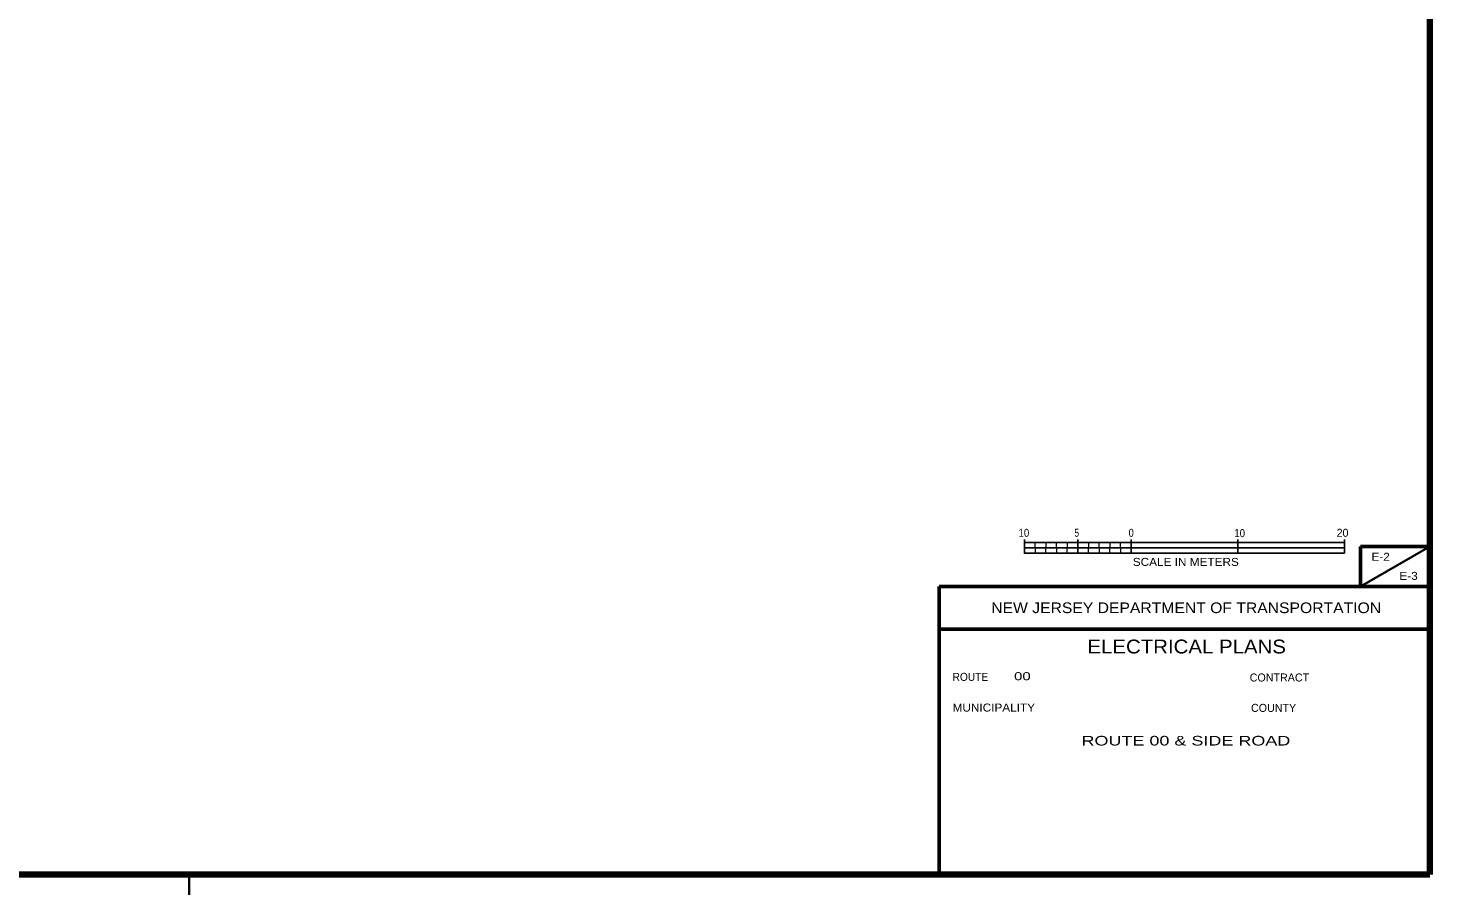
# Model space of a CAD drawing. Extents: x 168203 to 169863, y 223196 to 223870.
# Drawn here: x 169229.9 to 169361.3, y 223366.7 to 223448 of the extents above; entities that cross this region are included whole.
import ezdxf
from ezdxf.enums import TextEntityAlignment as Align

# ---------------------------------------------------------------- set-up
doc = ezdxf.new("R2010")
doc.units = 0
doc.header["$LTSCALE"] = 0.3
doc.layers.add('1', color=7, linetype='Continuous', lineweight=13)
doc.layers.add('25', color=7, linetype='Continuous', lineweight=35)

msp = doc.modelspace()

# ---------------------------------------------------------------- linework, layer by layer
at = {"layer": '1', "lineweight": 25}
for p, q in [((169323.2833, 223399.7226), (169353.2833, 223399.7226)), ((169325.1233, 223399.7226), (169326.1433, 223399.7226)), ((169327.1633, 223399.7226), (169328.1833, 223399.7226)), ((169328.2833, 223400.0201), (169328.2833, 223398.7226)), ((169329.2033, 223399.7226), (169330.2233, 223399.7226)), ((169331.2433, 223399.7226), (169332.2633, 223399.7226)), ((169333.2833, 223400.0201), (169333.2833, 223398.7226)), ((169343.2833, 223400.0201), (169343.2833, 223398.7226)), ((169353.2833, 223400.0201), (169353.2833, 223398.7226)), ((169323.2833, 223399.2226), (169353.2833, 223399.2226))]:
    msp.add_line(p, q, dxfattribs=at)
at = {"layer": '1', "lineweight": 35}
msp.add_line((169245.0333, 223368.6089), (169245.0333, 223366.6889), dxfattribs=at)
at = {"layer": '1', "lineweight": 158}
msp.add_lwpolyline([(169361.2833, 223368.6089), (169361.2833, 223530.6089), (169128.7833, 223530.6089), (169128.7833, 223368.6089)], close=True, dxfattribs=at)
at = {"layer": '1', "lineweight": 25}
msp.add_lwpolyline([(169323.2833, 223400.0201), (169323.2833, 223398.7226), (169353.2833, 223398.7226)], dxfattribs=at)
at = {"layer": '1'}
for points in [[(169323.2833, 223399.2226), (169324.2833, 223399.2226), (169324.2833, 223399.7226), (169323.2833, 223399.7226)], [(169325.2833, 223399.2226), (169326.2833, 223399.2226), (169326.2833, 223399.7226), (169325.2833, 223399.7226)], [(169327.2833, 223399.2226), (169328.2833, 223399.2226), (169328.2833, 223399.7226), (169327.2833, 223399.7226)], [(169329.2833, 223399.2226), (169330.2833, 223399.2226), (169330.2833, 223399.7226), (169329.2833, 223399.7226)], [(169331.2833, 223399.2226), (169332.2833, 223399.2226), (169332.2833, 223399.7226), (169331.2833, 223399.7226)], [(169333.2833, 223399.2226), (169343.2833, 223399.2226), (169343.2833, 223399.7226), (169333.2833, 223399.7226)], [(169324.2833, 223398.7226), (169325.2833, 223398.7226), (169325.2833, 223399.2226), (169324.2833, 223399.2226)], [(169326.2833, 223398.7226), (169327.2833, 223398.7226), (169327.2833, 223399.2226), (169326.2833, 223399.2226)], [(169328.2833, 223398.7226), (169329.2833, 223398.7226), (169329.2833, 223399.2226), (169328.2833, 223399.2226)], [(169330.2833, 223398.7226), (169331.2833, 223398.7226), (169331.2833, 223399.2226), (169330.2833, 223399.2226)], [(169332.2833, 223398.7226), (169333.2833, 223398.7226), (169333.2833, 223399.2226), (169332.2833, 223399.2226)], [(169343.2833, 223398.7226), (169353.2833, 223398.7226), (169353.2833, 223399.2226), (169343.2833, 223399.2226)]]:
    msp.add_lwpolyline(points, close=True, dxfattribs=at)
at = {"layer": '25'}
msp.add_line((169354.7833, 223395.6089), (169361.2833, 223399.3589), dxfattribs=at)
at = {"layer": '25', "lineweight": 53}
for p, q in [((169354.7833, 223399.3589), (169361.2833, 223399.3589)), ((169354.7833, 223399.3589), (169354.7833, 223395.6089)), ((169315.2833, 223368.6089), (169315.2833, 223395.6089)), ((169361.2833, 223395.6089), (169315.2833, 223395.6089)), ((169315.2833, 223391.6089), (169361.2833, 223391.6089))]:
    msp.add_line(p, q, dxfattribs=at)

# ---------------------------------------------------------------- texts
at = {"layer": '1'}
for s, width, p in [('10', 0.9, (169323.2342, 223400.2626)), ('5', 0.75, (169328.1859, 223400.2626)), ('0', 0.85, (169333.2884, 223400.2626)), ('10', 0.9, (169343.4542, 223400.2326)), ('SCALE IN METERS', 1.1, (169338.4047, 223397.5326))]:
    msp.add_text(s, height=0.7501, dxfattribs=dict(at, width=width)).set_placement(p, align=Align.CENTER)
msp.add_text('20', height=0.7501, dxfattribs=at).set_placement((169353.095, 223400.2626), align=Align.CENTER)
at = {"layer": '25'}
for s, height, width, p in [('E-2', 0.75, 1.1, (169356.6606, 223398.0129)), ('E-3', 0.75, 1.1, (169359.2798, 223396.2235)), ('NEW JERSEY DEPARTMENT OF TRANSPORTATION', 1, 1.1, (169338.4408, 223393.1089)), ('ELECTRICAL PLANS', 1.3, 1.1, (169338.488, 223389.3256)), ('             ROUTE 00 & SIDE ROAD            ', 0.9, 1.4, (169338.181, 223380.6989))]:
    msp.add_text(s, height=height, dxfattribs=dict(at, width=width)).set_placement(p, align=Align.CENTER)
for s, width, p in [('ROUTE', 0.95, (169316.5533, 223386.7589)), ('00                        ', 1.4, (169322.3133, 223386.8189)), ('MUNICIPALITY', 1.1, (169316.5533, 223383.8789))]:
    msp.add_text(s, height=0.75, dxfattribs=dict(at, width=width)).set_placement(p)
for s, p in [('CONTRACT', (169344.3933, 223386.6989)), ('COUNTY', (169344.5133, 223383.8489))]:
    msp.add_text(s, height=0.75, dxfattribs=at).set_placement(p)

doc.saveas('drawing.dxf')
